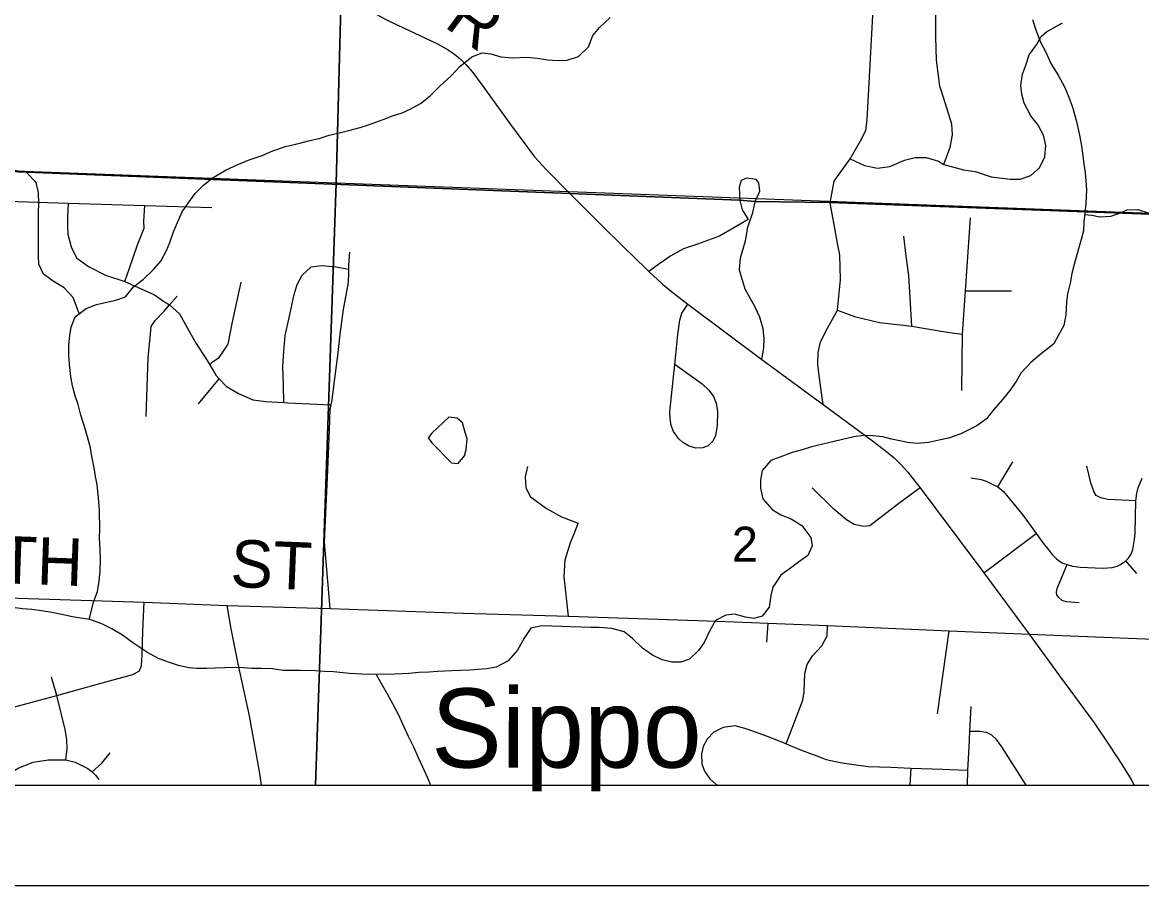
# Model space of a CAD drawing. Extents: x 0 to 34, y 0 to 22.
# Drawn here: x 6.833 to 8.174, y 14 to 15.034 of the extents above; entities that cross this region are included whole.
import ezdxf

# ---------------------------------------------------------------- set-up
doc = ezdxf.new("R2010")
doc.units = 0
for name, color, linetype in [('GM_X_Corporation', 7, 'Continuous'), ('GM_X_County_Road', 7, 'Continuous'), ('GM_X_County_Road_Text', 7, 'Continuous'), ('GM_X_Major_Lake_Text', 7, 'Continuous'), ('GM_X_Minor_Lake', 7, 'Continuous'), ('GM_X_Minor_River', 7, 'Continuous'), ('GM_X_Section_Text', 7, 'Continuous'), ('GM_X_Township_Road', 7, 'Continuous'), ('SH_Data', 7, 'Continuous')]:
    doc.layers.add(name, color=color, linetype=linetype)

msp = doc.modelspace()

# ---------------------------------------------------------------- linework, layer by layer
at = {"layer": 'GM_X_Corporation'}
for points in [[(7.1023, 20.9204), (2.837, 20.9204), (2.837, 14.1204), (9.637, 14.1204), (9.637, 20.9204), (9.4036, 20.9204), (9.4022, 20.8667), (9.2273, 20.8723), (9.1354, 20.8749), (9.124, 20.8753), (8.9858, 20.878), (8.9676, 20.8785), (8.8663, 20.881), (8.6259, 20.8892), (8.5535, 20.8914), (8.5421, 20.8915), (8.4667, 20.8934), (8.0602, 20.9055), (7.9522, 20.9084), (7.1104, 20.9188)], [(6.2042, 15.8911), (7.2356, 15.8559), (7.2089, 14.8416), (6.1854, 14.88)], [(8.2409, 15.8234), (8.2165, 14.8042), (7.2089, 14.8416), (7.2356, 15.8559)], [(6.1556, 14.1204), (7.184, 14.1204), (7.2089, 14.8416), (6.1854, 14.88)], [(7.184, 14.1204), (8.1915, 14.1204), (8.2165, 14.8042), (7.2089, 14.8416)]]:
    msp.add_lwpolyline(points, close=True, dxfattribs=at)
for points in [[(8.4248, 14.7958), (7.8005, 14.8186), (7.7106, 14.8199), (7.6921, 14.8213), (7.4889, 14.8294), (6.5635, 14.8658), (6.3152, 14.8755), (6.1855, 14.8807), (5.9592, 14.8856), (5.8117, 14.8915), (5.7258, 14.8953), (5.662, 14.8972), (5.3668, 14.9059), (5.2868, 14.911), (5.2181, 14.9126), (5.1335, 14.9126)], [(5.1335, 14.9126), (5.2181, 14.9126), (5.2868, 14.911), (5.3668, 14.9059), (5.662, 14.8972), (5.7258, 14.8953), (5.8117, 14.8915), (5.9592, 14.8856), (6.1855, 14.8807), (6.3152, 14.8755), (6.5635, 14.8658), (7.4889, 14.8294), (7.6921, 14.8213), (7.7106, 14.8199), (7.8005, 14.8186), (8.4248, 14.7958)], [(3.0474, 14.1204), (9.2101, 14.1204)]]:
    msp.add_lwpolyline(points, dxfattribs=at)
at = {"layer": 'GM_X_County_Road'}
for points in [[(7.1936, 15.0963), (7.2319, 15.0616), (7.2511, 15.0473), (7.2683, 15.0378), (7.3304, 15.0085), (7.3429, 15.0015), (7.3507, 14.9963), (7.3573, 14.9907), (7.3641, 14.9839), (7.3725, 14.9743), (7.3858, 14.9564), (7.4178, 14.9119), (7.4463, 14.8734), (7.4603, 14.8581), (7.4891, 14.8288), (7.5219, 14.7964), (7.556, 14.7627)], [(7.556, 14.7627), (7.5634, 14.7553), (7.5833, 14.736), (7.5993, 14.721), (7.6123, 14.7102), (7.63, 14.6967), (7.7188, 14.6306), (7.792, 14.5764), (7.8496, 14.5342), (7.8665, 14.5213), (7.8771, 14.5125), (7.8856, 14.5044), (7.8936, 14.4954), (7.9019, 14.4848), (7.9082, 14.4769), (7.9846, 14.3747), (8.0388, 14.3013), (8.0752, 14.2515), (8.1169, 14.1952), (8.1356, 14.1672), (8.1507, 14.144), (8.161, 14.1273), (8.1648, 14.1204)], [(6.3874, 14.359), (6.5426, 14.3539), (6.5792, 14.3522), (6.7516, 14.3468), (6.979, 14.3397), (7.0782, 14.3359), (7.2017, 14.3322), (7.361, 14.3265), (7.4872, 14.3228), (7.6653, 14.3168), (7.7263, 14.3144), (7.7972, 14.3116), (7.9431, 14.3054), (8.0388, 14.3013), (8.2574, 14.2927), (8.4556, 14.2841), (8.5559, 14.2812), (8.5818, 14.2806), (8.7041, 14.2756), (8.8353, 14.2719), (8.9607, 14.2676), (9.0887, 14.2645), (9.2143, 14.2602)]]:
    msp.add_lwpolyline(points, dxfattribs=at)
at = {"layer": 'GM_X_Minor_Lake'}
for points in [[(7.347, 14.5066), (7.3549, 14.506), (7.3624, 14.5152), (7.3646, 14.5228), (7.3659, 14.5354), (7.3632, 14.5429), (7.36, 14.5547), (7.3538, 14.5603), (7.3439, 14.5613), (7.3233, 14.5424), (7.3189, 14.5366), (7.3235, 14.5306)], [(7.3235, 14.5306), (7.347, 14.5066)]]:
    msp.add_lwpolyline(points, dxfattribs=at)
at = {"layer": 'GM_X_Minor_River'}
for points in [[(6.9132, 14.3191), (6.9186, 14.341), (6.923, 14.3525), (6.9251, 14.3651), (6.9261, 14.3772), (6.9267, 14.3913), (6.9262, 14.4019), (6.9256, 14.4171), (6.9258, 14.427), (6.9255, 14.4494), (6.9242, 14.465), (6.9228, 14.4802), (6.9208, 14.4904), (6.9191, 14.5006), (6.9163, 14.5143), (6.9146, 14.5245), (6.911, 14.5377), (6.9071, 14.5514), (6.9031, 14.5638), (6.8999, 14.5767), (6.8963, 14.5869), (6.8931, 14.599), (6.8911, 14.61), (6.8894, 14.6248), (6.8888, 14.6362), (6.8887, 14.648), (6.8897, 14.6594), (6.8914, 14.6693), (6.8962, 14.6815), (6.9093, 14.6916), (6.9218, 14.6963), (6.9324, 14.6988), (6.9449, 14.7016), (6.9566, 14.7056), (6.9663, 14.7175), (6.9783, 14.7268), (6.9903, 14.7383), (6.9988, 14.7483), (7.0055, 14.761), (7.0096, 14.7705), (7.0139, 14.7835), (7.0187, 14.7946), (7.0246, 14.8072), (7.0317, 14.8179), (7.0399, 14.8294), (7.05, 14.8395), (7.0605, 14.8476), (7.077, 14.8577), (7.0902, 14.8636), (7.1046, 14.8695), (7.1204, 14.875), (7.1332, 14.8805), (7.1483, 14.8857), (7.1654, 14.8897), (7.1756, 14.8925), (7.1896, 14.8958), (7.2005, 14.8993), (7.2126, 14.9022), (7.224, 14.905), (7.2376, 14.9086), (7.2478, 14.9118), (7.2651, 14.9181), (7.2764, 14.9224), (7.2878, 14.926), (7.2976, 14.9303), (7.31, 14.9373), (7.3216, 14.9462), (7.3336, 14.9582), (7.3467, 14.9705), (7.3568, 14.9817), (7.3715, 14.9929), (7.3839, 14.9977), (7.3942, 14.9967), (7.406, 14.993), (7.42, 14.9921), (7.4371, 14.9927), (7.4496, 14.9914), (7.4618, 14.9896), (7.4747, 14.9887), (7.4857, 14.9892), (7.4993, 14.9936), (7.5109, 15.0051), (7.5164, 15.0185), (7.5242, 15.0281), (7.537, 15.0401)], [(8.0427, 15.0377), (8.0471, 15.0244), (8.0525, 15.0108), (8.0588, 14.9988), (8.065, 14.9852), (8.0736, 14.9712), (8.0814, 14.9562), (8.0864, 14.9448), (8.0908, 14.9327), (8.0956, 14.9157), (8.0988, 14.9013), (8.1017, 14.8865), (8.103, 14.8744), (8.1042, 14.8645), (8.1059, 14.8547), (8.1068, 14.8444), (8.1077, 14.8338), (8.1068, 14.8174), (8.1054, 14.8056), (8.1044, 14.7954), (8.1038, 14.7847), (8.1013, 14.7741), (8.0962, 14.7576), (8.0926, 14.7443), (8.0901, 14.7336), (8.088, 14.7218), (8.0847, 14.7092), (8.0837, 14.6993), (8.0828, 14.6841), (8.0803, 14.6712), (8.0744, 14.6604), (8.0685, 14.6493), (8.0538, 14.6377), (8.0407, 14.6269), (8.0287, 14.6142), (8.0232, 14.6043), (8.0157, 14.5935), (8.0071, 14.5824), (7.9963, 14.5701), (7.9877, 14.5593), (7.9761, 14.5512), (7.9569, 14.5414), (7.9421, 14.5363), (7.9289, 14.5334), (7.9183, 14.531), (7.9043, 14.53), (7.8933, 14.531), (7.8838, 14.5332), (7.8739, 14.5349), (7.8636, 14.5378), (7.8518, 14.5392), (7.8404, 14.5394), (7.8287, 14.5377), (7.8136, 14.5341), (7.7984, 14.5308), (7.778, 14.526), (7.7671, 14.5224), (7.755, 14.5192), (7.7403, 14.5133), (7.7293, 14.5093), (7.7189, 14.4974), (7.7171, 14.4864), (7.7169, 14.4765), (7.7197, 14.4636), (7.7309, 14.4508), (7.7416, 14.4445), (7.7538, 14.4394), (7.7668, 14.4316), (7.7772, 14.4173), (7.7789, 14.4071), (7.7737, 14.3956), (7.7628, 14.3875), (7.7531, 14.3805), (7.7414, 14.372), (7.7317, 14.3578), (7.7296, 14.3479), (7.7275, 14.3338), (7.7189, 14.323), (7.7087, 14.3202), (7.6992, 14.3216), (7.6859, 14.3252), (7.6757, 14.3243), (7.6633, 14.3177), (7.6562, 14.305), (7.6496, 14.2913), (7.6429, 14.2817), (7.632, 14.2713), (7.6218, 14.2677), (7.6108, 14.2679), (7.5994, 14.2708), (7.5879, 14.2763)], [(6.9012, 14.6854), (6.894, 14.7047), (6.8832, 14.7163), (6.8713, 14.7234), (6.8583, 14.7327), (6.8528, 14.7448), (6.8523, 14.7542), (6.8522, 14.7668), (6.8524, 14.7801), (6.8525, 14.7949), (6.8524, 14.8063), (6.8526, 14.8169), (6.8524, 14.8306), (6.8496, 14.8427), (6.8381, 14.8544), (6.8206, 14.8575)], [(8.1053, 14.8043), (8.1138, 14.8035), (8.1237, 14.8013), (8.1366, 14.8023), (8.1464, 14.8055), (8.1562, 14.8098), (8.1691, 14.8103), (8.1813, 14.806), (8.1924, 14.7993), (8.2065, 14.793), (8.216, 14.789), (8.2298, 14.7835), (8.2599, 14.7624)], [(7.5879, 14.2763), (7.5757, 14.2845), (7.5638, 14.2961), (7.5538, 14.304), (7.5389, 14.3083), (7.5238, 14.3092), (7.5143, 14.3095), (7.5025, 14.3097), (7.4888, 14.3103), (7.4794, 14.3105), (7.4668, 14.3111), (7.4551, 14.3113), (7.4422, 14.3085), (7.434, 14.2966), (7.4259, 14.2824), (7.4147, 14.2693), (7.4007, 14.2619), (7.389, 14.2599), (7.3784, 14.259), (7.3689, 14.2584), (7.3583, 14.2579), (7.3469, 14.2574), (7.3302, 14.2568), (7.3204, 14.2559), (7.3079, 14.2553), (7.2961, 14.2544), (7.2791, 14.2534), (7.2476, 14.2529), (7.2248, 14.2541), (7.2058, 14.2562), (7.1944, 14.2568), (7.1842, 14.2574), (7.166, 14.2579), (7.1455, 14.258), (7.1326, 14.2597), (7.12, 14.2603), (7.1079, 14.2601), (7.0973, 14.2611), (7.0878, 14.2613), (7.0756, 14.2612), (7.0639, 14.2606), (7.0537, 14.2601), (7.0419, 14.2603), (7.0324, 14.2609), (7.0202, 14.2638), (7.008, 14.2678), (6.9962, 14.2722), (6.9821, 14.28), (6.9664, 14.2904), (6.953, 14.3001), (6.94, 14.3079), (6.9281, 14.3138), (6.914, 14.3189), (6.9026, 14.3207), (6.8931, 14.3221), (6.8805, 14.3249), (6.8684, 14.3274), (6.8558, 14.3295), (6.8444, 14.3309), (6.8334, 14.3319), (6.8186, 14.3339)], [(7.2567, 14.2531), (7.2641, 14.2403), (7.2699, 14.2301), (7.2765, 14.2184), (7.2835, 14.2048), (7.2898, 14.1905), (7.2953, 14.1791), (7.3015, 14.1663), (7.3066, 14.1546), (7.3124, 14.1425), (7.3183, 14.1293), (7.3219, 14.1204)]]:
    msp.add_lwpolyline(points, dxfattribs=at)
at = {"layer": 'GM_X_Township_Road'}
for p, q in [((7.6967, 14.8072), (7.7022, 14.7983)), ((7.9627, 14.7128), (8.0179, 14.7127)), ((7.0439, 14.5775), (7.0688, 14.6075)), ((8.0013, 14.4778), (8.0194, 14.5077)), ((7.9846, 14.3747), (8.0472, 14.4219)), ((8.1677, 14.3742), (8.1545, 14.3892)), ((7.7245, 14.292), (7.7263, 14.3144)), ((7.9292, 14.2061), (7.9431, 14.3054)), ((6.8742, 14.2278), (6.868, 14.2499)), ((7.8973, 14.1409), (7.8961, 14.1204))]:
    msp.add_line(p, q, dxfattribs=at)
for points in [[(7.8243, 14.8707), (7.8386, 14.8953), (7.8431, 14.9052), (7.845, 14.9175), (7.8542, 15.0872)], [(7.9367, 14.8642), (7.9441, 14.885), (7.9471, 14.8997), (7.9461, 14.9126), (7.9367, 14.9431), (7.9318, 14.9579), (7.9279, 14.989), (7.9271, 15.0172), (7.9269, 15.0335), (7.9272, 15.057), (7.929, 15.0726), (7.9318, 15.0788), (7.9366, 15.0849), (7.9422, 15.0885), (7.949, 15.0905), (7.9585, 15.0909), (7.9794, 15.0892), (7.9893, 15.0894), (8.1057, 15.0846), (8.1151, 15.0849), (8.1235, 15.0866), (8.13, 15.0894)], [(7.8243, 14.8707), (7.8416, 14.8628), (7.8574, 14.8598), (7.8721, 14.8618), (7.8894, 14.8692), (7.9022, 14.8726), (7.9155, 14.8726), (7.9303, 14.8682), (7.9367, 14.8642), (7.9604, 14.8578), (7.9742, 14.8559), (7.9934, 14.8495), (8.0161, 14.8465), (8.0279, 14.8465), (8.0407, 14.8509), (8.0511, 14.8603), (8.0575, 14.8731), (8.059, 14.8869), (8.056, 14.8992), (8.0496, 14.9111), (8.0407, 14.9224), (8.0329, 14.9377), (8.0299, 14.9485), (8.0289, 14.9589), (8.0309, 14.9722), (8.0343, 14.9821), (8.0388, 14.9954), (8.0476, 15.0074), (8.0532, 15.0175), (8.0598, 15.0231), (8.0788, 15.0337)], [(7.8098, 14.7673), (7.8081, 14.7765), (7.8007, 14.8181), (7.8054, 14.8442), (7.8243, 14.8707)], [(7.7116, 14.8214), (7.7161, 14.8322), (7.715, 14.8423), (7.7121, 14.8462), (7.7005, 14.8477), (7.6938, 14.8449), (7.6915, 14.8368), (7.6923, 14.8208), (7.695, 14.8098), (7.6967, 14.8072)], [(6.63, 14.8258), (6.6964, 14.8252), (6.761, 14.8218), (6.8272, 14.8197), (6.888, 14.8178), (6.9799, 14.815), (7.06, 14.8126)], [(6.888, 14.8178), (6.8871, 14.8014), (6.8871, 14.7912), (6.8874, 14.7805), (6.8915, 14.7654), (6.8979, 14.7521), (6.9122, 14.7418), (6.9326, 14.7315), (6.9558, 14.724), (6.9911, 14.7078), (7.0021, 14.7005), (7.0093, 14.6958), (7.0213, 14.6853), (7.0404, 14.6507), (7.0543, 14.6291), (7.0574, 14.624), (7.0649, 14.6116), (7.0688, 14.6075), (7.0773, 14.5987), (7.092, 14.5899), (7.109, 14.5823), (7.1245, 14.5803), (7.1463, 14.579), (7.151, 14.5787), (7.2027, 14.5761)], [(6.9558, 14.724), (6.9614, 14.7401), (6.9709, 14.7677), (6.9789, 14.7878), (6.9786, 14.7962), (6.9799, 14.815)], [(7.7188, 14.6306), (7.7211, 14.644), (7.7214, 14.6558), (7.7203, 14.6673), (7.7161, 14.6812), (7.7107, 14.6931), (7.6987, 14.7146), (7.6921, 14.7374), (7.6932, 14.7524), (7.699, 14.7726), (7.7019, 14.7891), (7.7078, 14.8065), (7.7108, 14.8194), (7.7116, 14.8214)], [(7.9581, 14.5933), (7.9592, 14.6608), (7.9627, 14.7128), (7.9687, 14.8004)], [(7.7022, 14.7983), (7.6679, 14.7781), (7.6415, 14.7687), (7.6248, 14.7632), (7.6099, 14.7545), (7.5954, 14.7447), (7.5833, 14.736)], [(7.8983, 14.6705), (7.8963, 14.7042), (7.8949, 14.7312), (7.8915, 14.7543), (7.8886, 14.7782)], [(7.2012, 14.5607), (7.2016, 14.5706), (7.2027, 14.5761), (7.2039, 14.5823), (7.2066, 14.6016), (7.2109, 14.635), (7.2136, 14.6607), (7.2175, 14.6903), (7.2237, 14.7229), (7.2241, 14.7343), (7.2241, 14.7388), (7.2242, 14.7434), (7.2254, 14.7589)], [(7.792, 14.5764), (7.7883, 14.6051), (7.7858, 14.6246), (7.7863, 14.6388), (7.7891, 14.6517), (7.7972, 14.668), (7.8095, 14.6897), (7.813, 14.7262), (7.812, 14.7558), (7.8098, 14.7673)], [(7.1538, 14.6861), (7.1586, 14.7083), (7.1621, 14.7205), (7.1682, 14.7314), (7.1788, 14.7416), (7.1913, 14.7431), (7.2083, 14.7415), (7.2241, 14.7388)], [(7.0574, 14.624), (7.0608, 14.6275), (7.0687, 14.6328), (7.0741, 14.6404), (7.0794, 14.6487), (7.0844, 14.6737), (7.0952, 14.7233)], [(6.9815, 14.5622), (6.9837, 14.6327), (6.986, 14.6566), (6.9872, 14.6699), (6.9921, 14.6774), (7.0028, 14.6884), (7.0093, 14.6958), (7.0183, 14.7062)], [(7.6149, 14.6244), (7.6473, 14.6014), (7.6554, 14.5938), (7.661, 14.5861), (7.664, 14.5781), (7.6656, 14.5681), (7.6651, 14.551), (7.6634, 14.5395), (7.6602, 14.5328), (7.6546, 14.5271), (7.6481, 14.5245), (7.6395, 14.5241), (7.631, 14.527), (7.6242, 14.5311), (7.6187, 14.5358), (7.6129, 14.5442), (7.6101, 14.5513), (7.6088, 14.5598), (7.6086, 14.5681), (7.6145, 14.6244), (7.6179, 14.6604), (7.6205, 14.6777), (7.623, 14.6859), (7.63, 14.6967)], [(7.1463, 14.579), (7.1457, 14.5992), (7.1451, 14.6219), (7.1463, 14.6401), (7.1479, 14.6591), (7.1538, 14.6861)], [(7.8095, 14.6897), (7.8297, 14.6818), (7.8598, 14.6749), (7.8983, 14.6705), (7.9333, 14.6646), (7.9466, 14.6626), (7.9592, 14.6608)], [(7.2017, 14.3322), (7.1949, 14.4117), (7.1986, 14.489), (7.2003, 14.5361), (7.2011, 14.5571), (7.2012, 14.5607)], [(7.438, 14.5022), (7.4353, 14.4901), (7.436, 14.4772), (7.4413, 14.4662), (7.4609, 14.4521), (7.4786, 14.4418), (7.4986, 14.4345)], [(8.1666, 14.4612), (8.1336, 14.4626), (8.1259, 14.4643), (8.1231, 14.4657), (8.1192, 14.4676), (8.1162, 14.4722), (8.1128, 14.4828), (8.1078, 14.5028)], [(7.9691, 14.4889), (7.9812, 14.4866), (7.9872, 14.4846), (7.9955, 14.4808), (8.0013, 14.4778), (8.008, 14.4722), (8.0315, 14.4436), (8.0412, 14.4302), (8.0472, 14.4219), (8.0558, 14.4104), (8.0623, 14.4021), (8.0665, 14.3969), (8.0717, 14.3915), (8.0754, 14.3888), (8.0793, 14.3866), (8.0843, 14.3847), (8.0908, 14.3829), (8.0999, 14.3816), (8.1179, 14.3807), (8.1277, 14.3805), (8.1383, 14.3812), (8.1441, 14.3829), (8.1482, 14.3847), (8.1545, 14.3892), (8.1575, 14.3922), (8.1609, 14.3972), (8.1631, 14.4028), (8.1652, 14.4147), (8.1657, 14.4223), (8.1666, 14.4612), (8.1677, 14.4705), (8.1693, 14.4766), (8.1741, 14.4883)], [(7.9082, 14.4769), (7.8829, 14.4578), (7.848, 14.431), (7.8404, 14.4303), (7.8291, 14.4326), (7.82, 14.4383), (7.805, 14.4513), (7.779, 14.4768)], [(7.4872, 14.3228), (7.4818, 14.3701), (7.483, 14.3906), (7.4895, 14.4111), (7.4948, 14.4236), (7.4986, 14.4345)], [(8.0986, 14.3391), (8.0834, 14.3401), (8.0809, 14.341), (8.0784, 14.3419), (8.0741, 14.3458), (8.0722, 14.3484), (8.0715, 14.3513), (8.0719, 14.3545), (8.0724, 14.356), (8.0754, 14.3628), (8.0843, 14.3847)], [(6.9732, 14.2575), (6.9757, 14.2638), (6.9764, 14.2765), (6.9775, 14.3048), (6.979, 14.3397)], [(7.1195, 14.1204), (7.1173, 14.1346), (7.105, 14.2034), (7.0916, 14.2658), (7.0832, 14.3076), (7.0782, 14.3359)], [(7.7478, 14.17), (7.7581, 14.1971), (7.7678, 14.2223), (7.7693, 14.2323), (7.77, 14.2542), (7.773, 14.2652), (7.7793, 14.2754), (7.7905, 14.2875), (7.7969, 14.2996), (7.7972, 14.3116)], [(6.6475, 14.1532), (6.6711, 14.1523), (6.6836, 14.1539), (6.6925, 14.1574), (6.7005, 14.1619), (6.7134, 14.1711), (6.7238, 14.1821), (6.7403, 14.191), (6.7585, 14.1963), (6.8056, 14.2094), (6.8742, 14.2278), (6.9286, 14.243), (6.9652, 14.2529), (6.9732, 14.2575)], [(6.8853, 14.1508), (6.8866, 14.1641), (6.8864, 14.1753), (6.8844, 14.187), (6.8742, 14.2278)], [(7.965, 14.1204), (7.9655, 14.1384), (7.9669, 14.1659), (7.9677, 14.1847), (7.9695, 14.2147)], [(7.7478, 14.17), (7.7244, 14.179), (7.7012, 14.1877), (7.6869, 14.1914), (7.6724, 14.1895), (7.6614, 14.1838), (7.6533, 14.1756), (7.6486, 14.1669), (7.6465, 14.1577), (7.6469, 14.1461), (7.6502, 14.1371), (7.6563, 14.1282), (7.6641, 14.1214), (7.6666, 14.1204)], [(8.0353, 14.1204), (8.0061, 14.1665), (7.9999, 14.1751), (7.994, 14.1802), (7.9876, 14.1835), (7.9797, 14.1847), (7.9677, 14.1847)], [(7.7478, 14.17), (7.765, 14.1627), (7.7846, 14.1556), (7.7958, 14.1513), (7.8126, 14.1477), (7.8287, 14.1452), (7.8461, 14.1429), (7.873, 14.142), (7.8973, 14.1409), (7.9353, 14.1397)], [(6.9168, 14.1363), (6.9284, 14.1468), (6.9382, 14.1594)], [(6.8018, 14.1204), (6.8165, 14.1339), (6.829, 14.1411), (6.8459, 14.148), (6.864, 14.1508), (6.8853, 14.1508)], [(6.8853, 14.1508), (6.8961, 14.1479), (6.9043, 14.1442), (6.9113, 14.1404), (6.9168, 14.1363)], [(6.9168, 14.1363), (6.9206, 14.1326), (6.9245, 14.1273)], [(7.9353, 14.1397), (7.9443, 14.1394), (7.9655, 14.1384)]]:
    msp.add_lwpolyline(points, dxfattribs=at)
at = {"layer": 'SH_Data'}
msp.add_line((2.7349, 14.0001), (9.7349, 14.0001), dxfattribs=at)

# ---------------------------------------------------------------- texts
at = {"layer": 'GM_X_County_Road_Text'}
for s, height, rotation, p in [('R', 0.0568, 323.5821, (7.3368, 15.0302)), ('12TH', 0.05682, 357.9567, (6.7189, 14.3656)), ('ST', 0.05682, 357.6399, (7.0816, 14.3582))]:
    msp.add_text(s, height=height, rotation=rotation, dxfattribs=at).set_placement(p)
at = {"layer": 'GM_X_Major_Lake_Text'}
msp.add_text('Sippo', height=0.09472, rotation=359.9763, dxfattribs=at).set_placement((7.3227, 14.1416))
at = {"layer": 'GM_X_Section_Text'}
msp.add_text('2', height=0.0419, rotation=0, dxfattribs=at).set_placement((7.6828, 14.3883))

doc.saveas('drawing.dxf')
